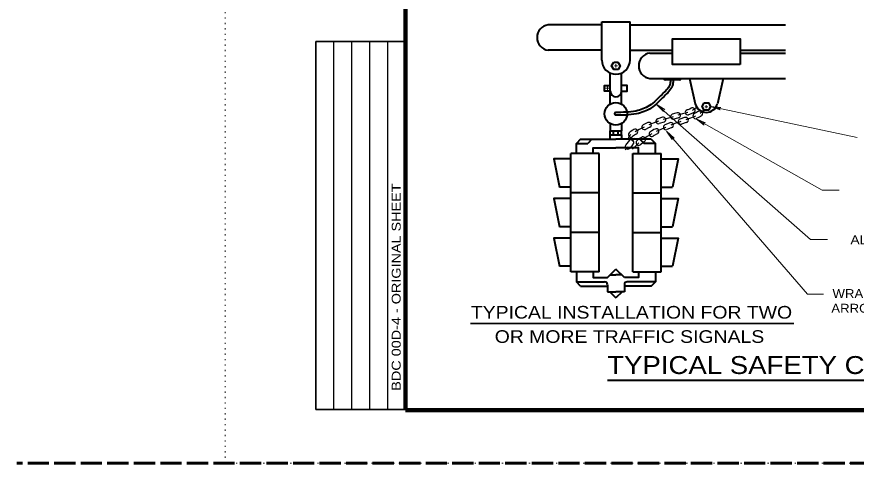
# Model space of a CAD drawing. Extents: x 312583 to 312854, y 144419 to 144597.
# Drawn here: x 312583.5 to 312654.7, y 144418.6 to 144456.5 of the extents above; entities that cross this region are included whole.
import ezdxf
from ezdxf.enums import TextEntityAlignment as Align

# ---------------------------------------------------------------- set-up
doc = ezdxf.new("R2010")
doc.units = 0
doc.header["$LTSCALE"] = 0.3
doc.linetypes.add('DOTTED', pattern=[1.5, 0.3, -1.2])
doc.linetypes.add('LONG_DASHED', pattern=[7.5, 6, -1.5])
for name, color, linetype, lineweight in [('1', 7, 'Continuous', 13), ('62', 7, 'DOTTED', 13), ('63', 7, 'LONG_DASHED', 60)]:
    doc.layers.add(name, color=color, linetype=linetype, lineweight=lineweight)

msp = doc.modelspace()

# ---------------------------------------------------------------- linework, layer by layer
at = {"layer": '1', "lineweight": 40}
for p, q in [((312633.1362, 144452.7839), (312633.1362, 144456.0192)), ((312633.1362, 144456.0192), (312635.5282, 144456.0192)), ((312635.5282, 144452.7839), (312635.5282, 144456.0192)), ((312633.1362, 144455.7739), (312628.5822, 144455.7739)), ((312635.5282, 144455.7739), (312648.7072, 144455.7739)), ((312633.1362, 144453.6196), (312628.5822, 144453.6196)), ((312635.5282, 144453.6196), (312639.1238, 144453.6196)), ((312637.2072, 144453.3819), (312639.1238, 144453.3819)), ((312644.8738, 144453.6196), (312648.7072, 144453.6196)), ((312644.8738, 144453.3819), (312648.7072, 144453.3819)), ((312633.8568, 144449.0579), (312633.8568, 144451.6799)), ((312634.8152, 144449.0579), (312634.8152, 144451.6799)), ((312637.2072, 144451.2276), (312648.7072, 144451.2276)), ((312639.7218, 144451.1049), (312638.5258, 144451.1049)), ((312640.5652, 144451.2276), (312641.0635, 144449.0886)), ((312643.4402, 144451.2276), (312642.9342, 144449.0886)), ((312633.8568, 144447.4019), (312633.8568, 144446.7886)), ((312633.8568, 144446.4359), (312633.8568, 144446.7886)), ((312633.8568, 144446.7886), (312634.8152, 144446.7886)), ((312634.1405, 144446.4359), (312634.1405, 144446.7886)), ((312634.5238, 144446.4359), (312634.5238, 144446.7886)), ((312634.8152, 144447.4019), (312634.8152, 144446.7886)), ((312634.8152, 144446.4359), (312634.8152, 144446.7886)), ((312631.3345, 144446.0756), (312634.3322, 144446.0756)), ((312632.2928, 144446.0756), (312631.9402, 144445.7152)), ((312633.8568, 144446.0756), (312633.8568, 144446.4359)), ((312633.8568, 144446.4359), (312634.8152, 144446.4359)), ((312637.3298, 144446.0756), (312634.3322, 144446.0756)), ((312634.8152, 144446.4359), (312634.8152, 144446.0756)), ((312636.3715, 144446.0756), (312636.7318, 144445.7152)), ((312630.9818, 144444.8719), (312630.9818, 144445.7152)), ((312637.6902, 144444.8719), (312637.6902, 144445.7152)), ((312632.8985, 144444.8719), (312630.4988, 144444.8719)), ((312630.4988, 144441.5216), (312630.4988, 144444.8719)), ((312632.8985, 144441.5216), (312632.8985, 144444.8719)), ((312635.7735, 144444.8719), (312638.1655, 144444.8719)), ((312635.7735, 144441.5216), (312635.7735, 144444.8719)), ((312638.1655, 144441.5216), (312638.1655, 144444.8719)), ((312630.4988, 144441.9969), (312629.5405, 144441.9969)), ((312638.1655, 144441.9969), (312639.1238, 144441.9969)), ((312632.8985, 144441.5216), (312630.4988, 144441.5216)), ((312630.4988, 144438.1636), (312630.4988, 144441.5216)), ((312632.8985, 144438.1636), (312632.8985, 144441.5216)), ((312635.7735, 144441.5216), (312638.1655, 144441.5216)), ((312635.7735, 144438.1636), (312635.7735, 144441.5216)), ((312638.1655, 144438.1636), (312638.1655, 144441.5216)), ((312630.4988, 144438.6466), (312629.5405, 144438.6466)), ((312638.1655, 144438.6466), (312639.1238, 144438.6466)), ((312630.4988, 144434.8132), (312630.4988, 144438.1636)), ((312638.1655, 144434.8132), (312638.1655, 144438.1636)), ((312630.4988, 144435.2886), (312629.5405, 144435.2886)), ((312632.8985, 144434.8132), (312630.4988, 144434.8132)), ((312630.9818, 144434.8132), (312630.9818, 144433.9776)), ((312633.6115, 144434.3302), (312634.3322, 144435.0509)), ((312635.0528, 144434.3302), (312634.3322, 144435.0509)), ((312635.7735, 144434.8132), (312638.1655, 144434.8132)), ((312637.6902, 144434.8132), (312637.6902, 144433.9776)), ((312638.1655, 144435.2886), (312639.1238, 144435.2886)), ((312633.8568, 144434.5756), (312634.3322, 144434.5756)), ((312634.8152, 144434.5756), (312634.3322, 144434.5756)), ((312631.3345, 144433.6172), (312633.6115, 144433.6172)), ((312633.6115, 144433.7322), (312633.6115, 144433.1342)), ((312635.0528, 144433.7322), (312635.0528, 144433.1342)), ((312637.3298, 144433.6172), (312635.0528, 144433.6172)), ((312633.6115, 144433.1342), (312634.3322, 144433.1342)), ((312633.8032, 144433.1342), (312634.3322, 144432.6052)), ((312635.0528, 144433.1342), (312634.3322, 144433.1342)), ((312634.8612, 144433.1342), (312634.3322, 144432.6052)), ((312633.6158, 144425.6362), (312680.3398, 144425.6362))]:
    msp.add_line(p, q, dxfattribs=at)
at = {"layer": '1', "lineweight": 25}
for p, q in [((312610.4087, 144423.1446), (312610.4087, 144454.3629)), ((312611.9315, 144423.1446), (312611.9315, 144454.3629)), ((312613.4543, 144423.1446), (312613.4543, 144454.3629)), ((312614.9772, 144423.1446), (312614.9772, 144454.3629)), ((312638.2882, 144447.9386), (312637.8742, 144447.8082)), ((312638.4185, 144447.5246), (312638.0045, 144447.3942))]:
    msp.add_line(p, q, dxfattribs=at)
at = {"layer": '1'}
for p, q in [((312634.3322, 144452.3009), (312634.3322, 144452.4312)), ((312634.3322, 144452.3009), (312634.2018, 144452.3009)), ((312634.3322, 144452.3009), (312634.4625, 144452.3009)), ((312634.3322, 144452.3009), (312634.3322, 144452.1706)), ((312633.6268, 144450.4072), (312633.3738, 144450.4072)), ((312633.6268, 144450.4072), (312633.6268, 144450.6219)), ((312633.6268, 144450.4072), (312633.8568, 144450.4072)), ((312633.6268, 144450.4072), (312633.6268, 144450.1466)), ((312650.8462, 144437.5579), (312637.7438, 144449.0349)), ((312637.7438, 144449.0349), (312638.3648, 144448.4216)), ((312637.7438, 144449.0349), (312638.4952, 144448.5902)), ((312641.9988, 144448.8279), (312641.9988, 144448.9582)), ((312638.3648, 144448.4216), (312638.2115, 144448.6746)), ((312638.4952, 144448.5902), (312638.2115, 144448.6746)), ((312641.9988, 144448.8279), (312641.8685, 144448.8279)), ((312641.9988, 144448.8279), (312642.1292, 144448.8279)), ((312641.9988, 144448.8279), (312641.9988, 144448.6976)), ((312654.7792, 144446.2136), (312642.3592, 144448.8432)), ((312642.3592, 144448.8432), (312643.2332, 144448.7666)), ((312642.3592, 144448.8432), (312643.1872, 144448.5596)), ((312643.2332, 144448.7666), (312642.9418, 144448.7206)), ((312643.1872, 144448.5596), (312642.9418, 144448.7206)), ((312641.1248, 144447.7929), (312641.8225, 144447.2716)), ((312641.1248, 144447.7929), (312641.9298, 144447.4632)), ((312641.8225, 144447.2716), (312641.6385, 144447.5016)), ((312641.9298, 144447.4632), (312641.6385, 144447.5016)), ((312638.6332, 144446.7579), (312639.1162, 144446.0372)), ((312638.6332, 144446.7579), (312639.2772, 144446.1752)), ((312639.1162, 144446.0372), (312639.0165, 144446.3132)), ((312639.2772, 144446.1752), (312639.0165, 144446.3132)), ((312652.2798, 144437.5579), (312650.8462, 144437.5579))]:
    msp.add_line(p, q, dxfattribs=at)
at = {"layer": '1', "lineweight": 35}
msp.add_line((312622.0118, 144430.4279), (312649.4087, 144430.4279), dxfattribs=at)
at = {"layer": '1', "lineweight": 158}
for points in [[(312616.5, 144423.0846), (312849, 144423.0846), (312849, 144585.0846)], [(312616.5, 144423.1446), (312616.5, 144585.0846), (312849, 144585.0846)]]:
    msp.add_lwpolyline(points, dxfattribs=at)
at = {"layer": '1', "lineweight": 40}
for points in [[(312644.8738, 144452.4236), (312639.1238, 144452.4236), (312639.1238, 144454.5779), (312644.8738, 144454.5779)], [(312634.1558, 144452.6152), (312634.5085, 144452.6152), (312634.6925, 144452.3009), (312634.5162, 144451.9942), (312634.1558, 144451.9942), (312633.9718, 144452.3009)], [(312641.8225, 144449.1576), (312642.1828, 144449.1576), (312642.3592, 144448.8432), (312642.1828, 144448.5366), (312641.8225, 144448.5289), (312641.6385, 144448.8432)]]:
    msp.add_lwpolyline(points, close=True, dxfattribs=at)
at = {"layer": '1', "lineweight": 35}
msp.add_lwpolyline([(312616.5, 144423.1446), (312608.8858, 144423.1446), (312608.8858, 144454.3629), (312616.5, 144454.3629)], dxfattribs=at)
at = {"layer": '1', "lineweight": 40}
for points in [[(312633.8568, 144450.1466), (312633.3738, 144450.1466), (312633.3738, 144450.6219), (312633.8568, 144450.6219)], [(312634.8152, 144450.1466), (312635.2905, 144450.1466), (312635.2905, 144450.6219), (312634.8152, 144450.6219)], [(312631.3345, 144446.0756), (312630.9818, 144445.7152), (312631.9402, 144445.7152)], [(312637.3298, 144446.0756), (312637.6902, 144445.7152), (312636.7318, 144445.7152)], [(312632.4155, 144444.8719), (312632.4155, 144445.3549), (312634.3322, 144445.3549)], [(312636.2488, 144444.8719), (312636.2488, 144445.3549), (312634.3322, 144445.3549)], [(312630.4988, 144444.3966), (312629.0652, 144444.3966), (312629.5405, 144441.9969)], [(312638.1655, 144444.3966), (312639.6068, 144444.3966), (312639.1238, 144441.9969)], [(312630.4988, 144441.0386), (312629.0652, 144441.0386), (312629.5405, 144438.6466)], [(312638.1655, 144441.0386), (312639.6068, 144441.0386), (312639.1238, 144438.6466)], [(312630.4988, 144437.6882), (312629.0652, 144437.6882), (312629.5405, 144435.2886)], [(312632.8985, 144434.8132), (312632.8985, 144438.1636), (312630.4988, 144438.1636)], [(312635.7735, 144434.8132), (312635.7735, 144438.1636), (312638.1655, 144438.1636)], [(312638.1655, 144437.6882), (312639.6068, 144437.6882), (312639.1238, 144435.2886)], [(312632.4155, 144434.8132), (312632.4155, 144434.3302), (312633.6115, 144434.3302)], [(312636.2488, 144434.8132), (312636.2488, 144434.3302), (312635.0528, 144434.3302)], [(312631.3345, 144433.6172), (312630.9818, 144433.9776), (312633.3738, 144433.9776)], [(312637.3298, 144433.6172), (312637.6902, 144433.9776), (312635.2905, 144433.9776)]]:
    msp.add_lwpolyline(points, dxfattribs=at)
at = {"layer": '1', "lineweight": 25}
for points in [[(312639.5378, 144448.3142), (312639.4228, 144448.2836), (312639.1162, 144448.1916)], [(312640.4272, 144448.3449), (312639.9902, 144448.2222), (312639.5915, 144448.1072)], [(312640.7185, 144448.7129), (312640.5882, 144448.6362), (312640.4272, 144448.5672), (312640.3735, 144448.5519)], [(312640.9332, 144448.3296), (312640.7722, 144448.2452), (312640.5652, 144448.1609), (312640.4885, 144448.1379)], [(312641.1862, 144448.7666), (312640.8565, 144448.5366), (312640.8258, 144448.5212)], [(312641.3472, 144448.4446), (312641.1785, 144448.3372), (312641.0022, 144448.2452), (312640.9945, 144448.2452)], [(312641.8225, 144448.5289), (312641.4775, 144448.2682), (312641.4698, 144448.2606)], [(312637.0462, 144447.4862), (312636.9158, 144447.4326), (312636.6398, 144447.2946)], [(312637.9355, 144447.6012), (312637.7055, 144447.5246), (312637.1305, 144447.2869)], [(312639.1775, 144447.9846), (312638.5948, 144447.8082), (312638.3495, 144447.7316)], [(312638.9092, 144447.4709), (312638.8402, 144447.4402), (312638.4952, 144447.3022)], [(312639.8292, 144447.5706), (312639.7755, 144447.5476), (312639.3308, 144447.3942), (312638.9935, 144447.2639)], [(312639.6528, 144447.9002), (312639.5455, 144447.8696), (312639.2388, 144447.7776)], [(312640.1742, 144447.9156), (312640.1512, 144447.9079), (312639.7602, 144447.7776)], [(312640.3352, 144447.5016), (312640.2968, 144447.4862), (312639.8982, 144447.3559)], [(312641.0865, 144448.0382), (312640.6648, 144447.8619), (312640.2508, 144447.7086)], [(312641.5925, 144448.0689), (312641.4085, 144447.9539), (312641.1938, 144447.8466), (312641.1708, 144447.8312)], [(312635.8655, 144446.8959), (312635.7735, 144446.8499), (312635.5512, 144446.7042), (312635.4668, 144446.6276)], [(312636.7395, 144447.1029), (312636.3178, 144446.8882), (312635.9652, 144446.7042)], [(312637.2148, 144447.0876), (312637.0922, 144447.0416), (312636.8315, 144446.9036)], [(312637.6595, 144446.9342), (312637.5598, 144446.8882), (312637.3452, 144446.7656), (312637.2608, 144446.7196)], [(312638.5795, 144447.0952), (312638.5258, 144447.0722), (312638.2038, 144446.9342), (312637.8818, 144446.7962), (312637.7592, 144446.7349)], [(312639.0778, 144447.0569), (312639.0088, 144447.0262), (312638.6638, 144446.8882)], [(312635.6048, 144446.4589), (312635.4975, 144446.3669), (312635.4515, 144446.3056), (312635.3978, 144446.2136), (312635.3595, 144446.1139)], [(312635.9115, 144446.1446), (312635.8578, 144446.0986), (312635.6738, 144445.9069)], [(312636.0648, 144446.5126), (312635.9958, 144446.4742), (312635.8195, 144446.3592), (312635.7505, 144446.2979)], [(312636.4942, 144446.2289), (312636.3715, 144446.1522), (312636.1185, 144445.9376)], [(312637.3682, 144446.5202), (312636.9695, 144446.2902), (312636.6168, 144446.0449)], [(312637.8588, 144446.5356), (312637.7668, 144446.4896), (312637.5675, 144446.3746), (312637.4832, 144446.3286)], [(312635.3595, 144445.4162), (312635.3135, 144445.3779), (312635.1295, 144445.1786)], [(312635.4668, 144445.9606), (312635.3902, 144445.8686), (312635.2368, 144445.6769), (312635.1755, 144445.6002)], [(312635.8042, 144445.6616), (312635.7352, 144445.5849), (312635.5895, 144445.4009), (312635.5282, 144445.3242)], [(312636.2642, 144445.7689), (312636.2182, 144445.7229), (312635.7428, 144445.2169)], [(312636.7395, 144445.8609), (312636.6398, 144445.7919), (312636.4098, 144445.6002)]]:
    msp.add_lwpolyline(points, dxfattribs=at)
at = {"layer": '1'}
for points in [[(312653.2535, 144441.7516), (312651.8122, 144441.7516), (312641.1095, 144447.8006)], [(312651.9348, 144432.9196), (312650.5778, 144432.9196), (312638.6332, 144446.7579)]]:
    msp.add_lwpolyline(points, dxfattribs=at)
at = {"layer": '1', "lineweight": 40}
msp.add_circle((312634.3322, 144448.2289), 0.9583, dxfattribs=at)
for centre, radius, start, end in [((312628.7346, 144454.6977), 1.0888, 98.04578, 261.95423), ((312637.3596, 144452.3019), 1.0888, 98.04578, 261.95423), ((312634.3322, 144452.781), 1.1979, 180, 0), ((312638.5249, 144451.2237), 0.1198, 180, 270), ((312639.7228, 144451.2237), 0.1198, 270, 0), ((312634.3322, 144450.1456), 0.4792, 180, 0), ((312641.9988, 144449.3068), 0.9581, 193.28615, 346.71385), ((312634.3322, 144448.2289), 0.1198, 90, 259.29865), ((312633.3738, 144433.7342), 0.2396, 0, 90), ((312635.2905, 144433.7342), 0.2396, 90, 180)]:
    msp.add_arc(centre, radius, start, end, dxfattribs=at)
at = {"layer": '1', "lineweight": 25}
for centre, radius, start, end in [((312639.1794, 144447.9858), 0.217, 106.80876, 286.80876), ((312639.5955, 144448.109), 0.217, 285.64546, 105.64546), ((312640.4299, 144448.346), 0.217, 106.04447, 286.04447), ((312640.8279, 144448.5166), 0.217, 305.01684, 125.01684), ((312641.0818, 144448.0368), 0.2232, 113.16566, 293.16566), ((312641.4686, 144448.2585), 0.2232, 307.75072, 127.75072), ((312637.1285, 144447.2861), 0.217, 292.62989, 112.62989), ((312637.9365, 144447.6002), 0.217, 107.61348, 287.61348), ((312638.3501, 144447.7315), 0.217, 287.61348, 107.61348), ((312638.9911, 144447.2608), 0.2232, 291.75162, 111.75162), ((312639.8288, 144447.5679), 0.2232, 109.02974, 289.02974), ((312640.2531, 144447.7062), 0.2232, 290.30305, 110.30305), ((312635.9647, 144446.7046), 0.217, 297.59492, 117.59492), ((312636.7369, 144447.0999), 0.217, 116.69353, 296.69353), ((312637.7595, 144446.7368), 0.2232, 296.63126, 116.63126), ((312638.5779, 144447.0921), 0.2232, 112.58365, 292.58365), ((312635.6065, 144446.4621), 0.217, 130.95638, 310.95638), ((312635.6326, 144445.8066), 0.2232, 318.63126, 138.63126), ((312636.6138, 144446.0461), 0.2232, 303.93366, 123.93366), ((312637.369, 144446.5208), 0.2232, 120.48689, 300.48689), ((312635.3515, 144445.46), 0.2232, 142.48689, 322.48689), ((312636.2603, 144445.7734), 0.2232, 136.88276, 316.88276)]:
    msp.add_arc(centre, radius, start, end, dxfattribs=at)
at = {"layer": '1', "lineweight": 40}
for points in [[(312639.2005, 144451.0589), (312639.1162, 144450.5759), (312638.4185, 144449.7096), (312637.3068, 144448.7129), (312636.0802, 144448.2299), (312634.3092, 144448.1072)], [(312638.9628, 144451.0896), (312638.8938, 144450.6756), (312638.2422, 144449.8782), (312637.1765, 144448.9199), (312636.0265, 144448.4599), (312634.3322, 144448.3526)]]:
    msp.add_spline(points, degree=3, dxfattribs=at)
at = {"layer": '62'}
msp.add_line((312601.2, 144418.5846), (312601.2, 144596.7846), dxfattribs=at)
msp.add_lwpolyline([(312601.2, 144418.5846), (312853.5, 144418.5846), (312853.5, 144596.7846)], dxfattribs=at)
at = {"layer": '63'}
msp.add_line((312851.75, 144418.5846), (312583.526, 144418.5846), dxfattribs=at)

# ---------------------------------------------------------------- texts
at = {"layer": '1', "width": 1.2}
msp.add_text('BDC 00D-4 - ORIGINAL SHEET', height=0.7614, rotation=90, dxfattribs=at).set_placement((312616.0832, 144424.7374))
at = {"layer": '1'}
for s, height, width, p in [('ALLOW 610 MM SLACK', 0.76, 1.15, (312654.2207, 144437.1602)), ('WRAP CHAIN ONE TURN', 0.76, 1.1, (312652.6986, 144432.5966)), ('ARROUND SPIDER ASSEMBLY', 0.76, 1.1, (312652.5977, 144431.3489)), ('TYPICAL SAFETY CHAIN INSTALLATIONS', 1.52, 1.15, (312633.5952, 144426.1538))]:
    msp.add_text(s, height=height, dxfattribs=dict(at, width=width)).set_placement(p)
at = {"layer": '1', "width": 1.15}
for s, p in [('TYPICAL INSTALLATION FOR TWO', (312635.6526, 144430.8551)), ('OR MORE TRAFFIC SIGNALS', (312635.4828, 144428.7956))]:
    msp.add_text(s, height=1.07, dxfattribs=at).set_placement(p, align=Align.CENTER)

doc.saveas('drawing.dxf')
